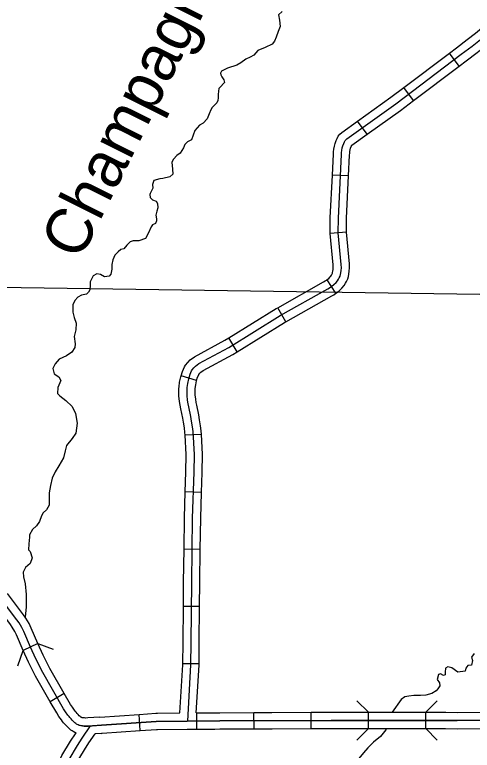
# Model space of a CAD drawing. Extents: x -492261 to -432772, y 1441225 to 1452922.
# Drawn here: x -458962.3 to -458841.6, y 1451430.4 to 1451624.2 of the extents above; entities that cross this region are included whole.
import ezdxf

# ---------------------------------------------------------------- set-up
doc = ezdxf.new("R2010")
doc.units = 0
doc.layers.add('Default', color=7, linetype='Continuous')

msp = doc.modelspace()

# ---------------------------------------------------------------- linework, layer by layer
at = {"layer": 'Default'}
for p, q in [((-458845.09, 1451610.65), (-458847.67, 1451614.06)), ((-458857.12, 1451601.54), (-458859.7, 1451604.96)), ((-458869.38, 1451592.66), (-458871.87, 1451596.15)), ((-458874.26, 1451581.68), (-458878.54, 1451581.89)), ((-458874.84, 1451566.91), (-458879.11, 1451566.51)), ((-458877.61, 1451550.78), (-458879.94, 1451554.37)), ((-458890.84, 1451543.25), (-458892.94, 1451546.98)), ((-458903.61, 1451535.39), (-458905.86, 1451539.04)), ((-458914.32, 1451527.78), (-458918.42, 1451529.01)), ((-458913.06, 1451513.62), (-458917.34, 1451513.37)), ((-458913.02, 1451498.35), (-458917.3, 1451498.49)), ((-458913.36, 1451483.31), (-458917.64, 1451483.37)), ((-458913.53, 1451468.24), (-458917.82, 1451468.27)), ((-458956.15, 1451458.5), (-458960.03, 1451456.68)), ((-458913.69, 1451453.14), (-458917.97, 1451453.2)), ((-458949.2, 1451445.33), (-458952.91, 1451443.19)), ((-458914.26, 1451435.98), (-458914.28, 1451440.26)), ((-458899.18, 1451436.05), (-458899.2, 1451440.33)), ((-458884.09, 1451436.11), (-458884.11, 1451440.4)), ((-458869.02, 1451436.14), (-458869.02, 1451440.42)), ((-458853.93, 1451436.14), (-458853.93, 1451440.42)), ((-458929.2, 1451435.58), (-458929.5, 1451439.85))]:
    msp.add_line(p, q, dxfattribs=at)
for points in [[(-458891.73, 1451624.99), (-458892.71, 1451624.09), (-458892.43, 1451622.77), (-458892.28, 1451621.03), (-458892.85, 1451619.76), (-458893.39, 1451618.26), (-458893.77, 1451617.22), (-458894.43, 1451616.43), (-458896.21, 1451615.54), (-458898.14, 1451614.73), (-458899.28, 1451613.5), (-458900.19, 1451612.94), (-458901.38, 1451612.49), (-458902.7, 1451611.51), (-458903.74, 1451610.86), (-458906.21, 1451610.07), (-458907.76, 1451609.32), (-458908.01, 1451608.76)], [(-458847.67, 1451614.06), (-458845.85, 1451615.44), (-458842.97, 1451617.6), (-458840.83, 1451619.29), (-458839.78, 1451620.14), (-458838.5, 1451621.24), (-458836.61, 1451622.99), (-458836.19, 1451623.41)], [(-458845.09, 1451610.65), (-458843.27, 1451612.02), (-458840.36, 1451614.2), (-458838.15, 1451615.94), (-458837.04, 1451616.84), (-458835.64, 1451618.04), (-458833.65, 1451619.89), (-458833.19, 1451620.34)], [(-458916.68, 1451438.11), (-458915.83, 1451452.87), (-458915.76, 1451458.81), (-458915.62, 1451474.67), (-458915.39, 1451491.57), (-458914.98, 1451503.65), (-458914.9, 1451508.32), (-458915.25, 1451514.34), (-458915.41, 1451515.59), (-458915.64, 1451517.14), (-458915.84, 1451518.34), (-458916.38, 1451520.83), (-458916.56, 1451521.66), (-458916.69, 1451522.59), (-458916.84, 1451523.87), (-458916.83, 1451525.65), (-458916.81, 1451525.94), (-458916.68, 1451527.05), (-458916.41, 1451528.26), (-458916.06, 1451529.45), (-458915.63, 1451530.36), (-458915.47, 1451530.62), (-458915.05, 1451531.17), (-458914.61, 1451531.62), (-458913.71, 1451532.27), (-458905.84, 1451536.54), (-458892.27, 1451544.9), (-458879.75, 1451551.95), (-458879.31, 1451552.22), (-458878.67, 1451552.64), (-458878.11, 1451553.08), (-458877.55, 1451553.6), (-458877.16, 1451554.06), (-458876.91, 1451554.48), (-458876.72, 1451554.84), (-458876.52, 1451555.33), (-458876.39, 1451555.75), (-458876.29, 1451556.2), (-458876.2, 1451556.82), (-458876.17, 1451557.49), (-458876.19, 1451558.38), (-458876.98, 1451566.73), (-458876.93, 1451570.6), (-458876.13, 1451587.31), (-458876.1, 1451587.87), (-458876.04, 1451588.42), (-458875.92, 1451589.07), (-458875.77, 1451589.62), (-458875.55, 1451590.25), (-458875.37, 1451590.67), (-458875.2, 1451591), (-458875.01, 1451591.23), (-458874.74, 1451591.48), (-458861.81, 1451600.68), (-458844.56, 1451613.73), (-458841.67, 1451615.9), (-458839.49, 1451617.61)], [(-458859.7, 1451604.96), (-458847.67, 1451614.06)], [(-458857.12, 1451601.54), (-458845.09, 1451610.65)], [(-458908.01, 1451608.76), (-458907.92, 1451608.29), (-458907.71, 1451607.83), (-458907.15, 1451607.04), (-458906.96, 1451606.33), (-458907.21, 1451606.04), (-458907.9, 1451605.28), (-458908.43, 1451604.69), (-458908.53, 1451604.03), (-458908.65, 1451603.14), (-458908.65, 1451602.25), (-458908.69, 1451601.56), (-458908.99, 1451600.95), (-458910.25, 1451599.68), (-458910.61, 1451599.13), (-458911.04, 1451598.09), (-458911.58, 1451596.78), (-458912.57, 1451595.58), (-458913.53, 1451595.1), (-458914.76, 1451593.69), (-458915.64, 1451591.2), (-458916.71, 1451590.69), (-458917.41, 1451590.01), (-458917.81, 1451589.06), (-458918.69, 1451587.66), (-458919.56, 1451587.04), (-458920.4, 1451586.1), (-458920.83, 1451585.28), (-458920.65, 1451583.51), (-458920.61, 1451582.19), (-458921.37, 1451581.46), (-458923.19, 1451581.04), (-458924.04, 1451580.93), (-458925.6, 1451580.49), (-458925.92, 1451579.45), (-458925.84, 1451578.51), (-458926.25, 1451577.75), (-458926.6, 1451577.05), (-458926.65, 1451576.82), (-458926.55, 1451575.99), (-458925.93, 1451575.41), (-458924.98, 1451575.03), (-458924.62, 1451574.46), (-458924.56, 1451573.32), (-458924.8, 1451572.42), (-458925.03, 1451571.36), (-458924.92, 1451570.36), (-458924.9, 1451569.9), (-458925.17, 1451569.2), (-458925.91, 1451568.78), (-458926.32, 1451568.26), (-458927.05, 1451566.52), (-458927.82, 1451565.18), (-458929.57, 1451564.62), (-458931.06, 1451564.58), (-458931.83, 1451564.31), (-458932.72, 1451563.45), (-458933.55, 1451562.52), (-458934.29, 1451562.3), (-458934.99, 1451561.68), (-458935.85, 1451560.79), (-458936.43, 1451559.63), (-458936.71, 1451558.39), (-458936.69, 1451557.73), (-458936.7, 1451557.13), (-458936.93, 1451555.84), (-458937.37, 1451555.28), (-458938.57, 1451555.11), (-458939.7, 1451555.74), (-458940.62, 1451555.89), (-458941.61, 1451555.38), (-458942.34, 1451553.81), (-458942.4, 1451552.8), (-458942.49, 1451551.68), (-458942.81, 1451551.04), (-458943.34, 1451550.54), (-458944.65, 1451550.25), (-458945.61, 1451549.74), (-458946.42, 1451548.86), (-458946.93, 1451547.73), (-458946.94, 1451545.78), (-458946.6, 1451544.43)], [(-458871.87, 1451596.15), (-458863.08, 1451602.41), (-458859.7, 1451604.96)], [(-458869.38, 1451592.66), (-458860.54, 1451598.95), (-458857.12, 1451601.54)], [(-458878.54, 1451581.89), (-458878.27, 1451587.43), (-458878.23, 1451588.04), (-458878.16, 1451588.73), (-458878.01, 1451589.54), (-458877.82, 1451590.26), (-458877.55, 1451591.03), (-458877.31, 1451591.59), (-458876.99, 1451592.19), (-458876.57, 1451592.71), (-458876.08, 1451593.15), (-458871.87, 1451596.15)], [(-458874.26, 1451581.68), (-458873.99, 1451587.2), (-458873.96, 1451587.69), (-458873.92, 1451588.11), (-458873.83, 1451588.6), (-458873.72, 1451588.98), (-458873.55, 1451589.47), (-458873.44, 1451589.74), (-458873.42, 1451589.78), (-458873.39, 1451589.8), (-458869.38, 1451592.66)], [(-458879.11, 1451566.51), (-458879.12, 1451566.64), (-458879.08, 1451570.67), (-458878.54, 1451581.89)], [(-458874.84, 1451566.82), (-458874.79, 1451570.54), (-458874.26, 1451581.68)], [(-458879.94, 1451554.37), (-458879.93, 1451554.38), (-458879.5, 1451554.71), (-458879.1, 1451555.08), (-458878.92, 1451555.3), (-458878.78, 1451555.53), (-458878.66, 1451555.76), (-458878.54, 1451556.05), (-458878.47, 1451556.29), (-458878.4, 1451556.59), (-458878.34, 1451557.02), (-458878.32, 1451557.51), (-458878.34, 1451558.25), (-458879.11, 1451566.51)], [(-458877.61, 1451550.78), (-458877.42, 1451550.89), (-458876.72, 1451551.45), (-458876, 1451552.12), (-458875.41, 1451552.81), (-458875.04, 1451553.43), (-458874.78, 1451553.93), (-458874.5, 1451554.61), (-458874.32, 1451555.2), (-458874.18, 1451555.81), (-458874.07, 1451556.62), (-458874.03, 1451557.47), (-458874.05, 1451558.5), (-458874.84, 1451566.91)], [(-458990.86, 1451552.72), (-458839.69, 1451550.51)], [(-458892.94, 1451546.98), (-458880.84, 1451553.8), (-458880.46, 1451554.03), (-458879.94, 1451554.37)], [(-458890.84, 1451543.25), (-458878.66, 1451550.11), (-458878.16, 1451550.41), (-458877.61, 1451550.78)], [(-458905.86, 1451539.04), (-458893.36, 1451546.75), (-458892.94, 1451546.98)], [(-458946.6, 1451544.43), (-458946.04, 1451542.93), (-458946.19, 1451541.18), (-458946.6, 1451539.37), (-458946.36, 1451537.46), (-458946.39, 1451536.54), (-458947.19, 1451535.24), (-458948.62, 1451534.34), (-458950.56, 1451533.43), (-458951.64, 1451532.21), (-458952.24, 1451530.93), (-458951.83, 1451529.54), (-458950.64, 1451528.8), (-458950.11, 1451527.84), (-458950.94, 1451525.96), (-458950.99, 1451524.39), (-458950.37, 1451523.78), (-458948.78, 1451522.53), (-458947.17, 1451520.97), (-458946.21, 1451519.11), (-458945.77, 1451516.61), (-458946.16, 1451513.97), (-458947.1, 1451512.57), (-458948.59, 1451510.7), (-458948.98, 1451509.26), (-458949.39, 1451507.45), (-458950.62, 1451505.33), (-458951.58, 1451503.79), (-458952.42, 1451502.11), (-458952.8, 1451500.16), (-458953.21, 1451498.26), (-458953.17, 1451496.84), (-458953.18, 1451494.95), (-458953.86, 1451493.7), (-458954.73, 1451492.96), (-458955.22, 1451492.15), (-458955.73, 1451490.71), (-458956.55, 1451489.52), (-458957.61, 1451488.57), (-458958.38, 1451487.18), (-458958.36, 1451486.58), (-458958.54, 1451484.75), (-458958.68, 1451483.2), (-458958.24, 1451482.76), (-458957.71, 1451481.08), (-458958.24, 1451479.61), (-458959.44, 1451478.55), (-458960.01, 1451477.31), (-458959.99, 1451476.06), (-458959.55, 1451474.28), (-458959.29, 1451471.48), (-458959.23, 1451468.16), (-458959.53, 1451465.47)], [(-458903.61, 1451535.39), (-458891.18, 1451543.06), (-458890.84, 1451543.25)], [(-458918.42, 1451529.01), (-458918.06, 1451530.21), (-458917.52, 1451531.38), (-458917.24, 1451531.83), (-458916.67, 1451532.59), (-458916, 1451533.25), (-458914.85, 1451534.08), (-458906.91, 1451538.39), (-458905.86, 1451539.04)], [(-458914.32, 1451527.78), (-458914.05, 1451528.68), (-458913.75, 1451529.33), (-458913.7, 1451529.41), (-458913.43, 1451529.76), (-458913.22, 1451529.98), (-458912.56, 1451530.45), (-458904.76, 1451534.68), (-458903.61, 1451535.39)], [(-458917.34, 1451513.37), (-458917.39, 1451514.14), (-458917.53, 1451515.3), (-458917.76, 1451516.8), (-458917.95, 1451517.93), (-458918.48, 1451520.38), (-458918.67, 1451521.28), (-458918.82, 1451522.31), (-458918.98, 1451523.76), (-458918.97, 1451525.74), (-458918.94, 1451526.14), (-458918.79, 1451527.4), (-458918.49, 1451528.8), (-458918.42, 1451529.01)], [(-458913.06, 1451513.62), (-458913.12, 1451514.53), (-458913.28, 1451515.88), (-458913.52, 1451517.48), (-458913.74, 1451518.74), (-458914.29, 1451521.28), (-458914.45, 1451522.04), (-458914.57, 1451522.86), (-458914.7, 1451523.99), (-458914.69, 1451525.57), (-458914.67, 1451525.74), (-458914.56, 1451526.69), (-458914.34, 1451527.72), (-458914.32, 1451527.78)], [(-458917.3, 1451498.49), (-458917.12, 1451503.7), (-458917.04, 1451508.28), (-458917.34, 1451513.37)], [(-458913.02, 1451498.35), (-458912.84, 1451503.59), (-458912.76, 1451508.37), (-458913.06, 1451513.62)], [(-458917.64, 1451483.37), (-458917.53, 1451491.62), (-458917.3, 1451498.49)], [(-458913.36, 1451483.31), (-458913.25, 1451491.52), (-458913.02, 1451498.35)], [(-458917.82, 1451468.27), (-458917.76, 1451474.69), (-458917.64, 1451483.37)], [(-458913.53, 1451468.24), (-458913.47, 1451474.65), (-458913.36, 1451483.31)], [(-458956.15, 1451458.5), (-458957.92, 1451462.61), (-458958.47, 1451463.78), (-458959.35, 1451465.18), (-458959.96, 1451466.04), (-458964.2, 1451471.66)], [(-458939.38, 1451437.02), (-458942.92, 1451436.78), (-458943.57, 1451436.76), (-458943.96, 1451436.76), (-458944.38, 1451436.8), (-458944.72, 1451436.84), (-458944.99, 1451436.89), (-458945.25, 1451436.97), (-458945.53, 1451437.07), (-458945.81, 1451437.22), (-458945.97, 1451437.32), (-458946.14, 1451437.44), (-458946.4, 1451437.65), (-458946.74, 1451437.95), (-458947.11, 1451438.32), (-458947.42, 1451438.66), (-458947.74, 1451439.04), (-458947.95, 1451439.3), (-458948.24, 1451439.69), (-458948.85, 1451440.53), (-458949.38, 1451441.36), (-458954.9, 1451450.91), (-458956.67, 1451454.5), (-458958.09, 1451457.58), (-458959.87, 1451461.73), (-458960.36, 1451462.75), (-458961.13, 1451463.99), (-458961.69, 1451464.77), (-458965.73, 1451470.1)], [(-458939.38, 1451437.02), (-458942.92, 1451436.78), (-458943.57, 1451436.76), (-458943.96, 1451436.76), (-458944.38, 1451436.8), (-458944.72, 1451436.84), (-458944.99, 1451436.89), (-458945.25, 1451436.97), (-458945.53, 1451437.07), (-458945.81, 1451437.22), (-458945.97, 1451437.32), (-458946.14, 1451437.44), (-458946.4, 1451437.65), (-458946.74, 1451437.95), (-458947.11, 1451438.32), (-458947.42, 1451438.66), (-458947.74, 1451439.04), (-458947.95, 1451439.3), (-458948.24, 1451439.69), (-458948.85, 1451440.53), (-458949.38, 1451441.36), (-458954.9, 1451450.91), (-458956.67, 1451454.5), (-458958.09, 1451457.58), (-458959.87, 1451461.73), (-458960.36, 1451462.75), (-458961.13, 1451463.99), (-458961.69, 1451464.77), (-458965.73, 1451470.1)], [(-458960.03, 1451456.68), (-458961.83, 1451460.85), (-458962.24, 1451461.72), (-458962.91, 1451462.8), (-458963.42, 1451463.5), (-458967.47, 1451468.85), (-458967.64, 1451469.1)], [(-458917.97, 1451453.2), (-458917.9, 1451458.83), (-458917.82, 1451468.27)], [(-458913.69, 1451453.14), (-458913.61, 1451458.79), (-458913.53, 1451468.24)], [(-458949.2, 1451445.33), (-458953.01, 1451451.92), (-458954.73, 1451455.42), (-458956.15, 1451458.5)], [(-458956.15, 1451458.5), (-458952.12, 1451457.04)], [(-458961.49, 1451452.65), (-458960.03, 1451456.68)], [(-458952.91, 1451443.19), (-458956.79, 1451449.9), (-458958.6, 1451453.57), (-458960.03, 1451456.68)], [(-458841.18, 1451455.87), (-458841.88, 1451454.97), (-458841.59, 1451454.03), (-458841.85, 1451452.79), (-458842.82, 1451452.71), (-458843.32, 1451452.03), (-458843.52, 1451451.2), (-458845.49, 1451450.95), (-458847.04, 1451452.09), (-458848.1, 1451452.35), (-458848.69, 1451452.04), (-458848.84, 1451450.95), (-458848.82, 1451450.32), (-458849.24, 1451450.08), (-458850, 1451450.55), (-458850.59, 1451450.33), (-458850.88, 1451449.04), (-458850.28, 1451448.16), (-458850.18, 1451447.39), (-458850.73, 1451446.6), (-458851.17, 1451446.1), (-458852.3, 1451445.4), (-458853.9, 1451444.96), (-458855.31, 1451444.83), (-458857.1, 1451444.83), (-458858.34, 1451444.69), (-458859.41, 1451444.51), (-458860.38, 1451443.75), (-458862.76, 1451440.42)], [(-458918.71, 1451440.23), (-458917.98, 1451452.95), (-458917.97, 1451453.2)], [(-458914.41, 1451440.26), (-458913.69, 1451452.8), (-458913.69, 1451453.14)], [(-458939.81, 1451439.14), (-458943.02, 1451438.92), (-458943.58, 1451438.9), (-458943.86, 1451438.91), (-458944.15, 1451438.93), (-458944.37, 1451438.96), (-458944.5, 1451438.98), (-458944.59, 1451439.01), (-458944.66, 1451439.03), (-458944.75, 1451439.08), (-458944.78, 1451439.1), (-458944.83, 1451439.14), (-458945.02, 1451439.29), (-458945.26, 1451439.51), (-458945.57, 1451439.81), (-458945.81, 1451440.08), (-458946.1, 1451440.41), (-458946.27, 1451440.62), (-458946.52, 1451440.95), (-458947.07, 1451441.73), (-458947.55, 1451442.48), (-458949.2, 1451445.33)], [(-458946.11, 1451435), (-458946.41, 1451435.11), (-458946.87, 1451435.35), (-458947.17, 1451435.54), (-458947.44, 1451435.74), (-458947.79, 1451436.02), (-458948.21, 1451436.4), (-458948.66, 1451436.84), (-458949.03, 1451437.25), (-458949.39, 1451437.67), (-458949.64, 1451437.97), (-458949.97, 1451438.42), (-458950.62, 1451439.33), (-458951.21, 1451440.25), (-458952.91, 1451443.19)], [(-458872.05, 1451443.45), (-458869.02, 1451440.42)], [(-458853.93, 1451440.42), (-458850.9, 1451443.45)], [(-458914.41, 1451440.26), (-458914.28, 1451440.26)], [(-458914.28, 1451440.26), (-458909.54, 1451440.29), (-458908.18, 1451440.29), (-458899.2, 1451440.33)], [(-458899.2, 1451440.33), (-458894.45, 1451440.35), (-458884.11, 1451440.4)], [(-458884.11, 1451440.4), (-458879.36, 1451440.42), (-458878.86, 1451440.42), (-458869.02, 1451440.42)], [(-458869.02, 1451440.42), (-458864.27, 1451440.42), (-458853.93, 1451440.42)], [(-458853.93, 1451440.42), (-458849.18, 1451440.42), (-458848.63, 1451440.42), (-458845.61, 1451440.36), (-458838.87, 1451440.43)], [(-458939.81, 1451439.14), (-458929.5, 1451439.85)], [(-458832.84, 1451438.36), (-458845.62, 1451438.21), (-458848.66, 1451438.28), (-458878.86, 1451438.28), (-458908.17, 1451438.15), (-458916.8, 1451438.11), (-458924.95, 1451438.02), (-458939.38, 1451437.02)], [(-458832.84, 1451438.36), (-458845.62, 1451438.21), (-458848.66, 1451438.28), (-458878.86, 1451438.28), (-458908.17, 1451438.15), (-458916.8, 1451438.11), (-458924.95, 1451438.02), (-458939.38, 1451437.02)], [(-458929.5, 1451439.85), (-458925.04, 1451440.16), (-458924.63, 1451440.17), (-458918.71, 1451440.23)], [(-458849.18, 1451438.28), (-458848.66, 1451438.28), (-458845.62, 1451438.21), (-458834.1, 1451438.34)], [(-458947.96, 1451427.94), (-458945.71, 1451431.68), (-458944.48, 1451433.58), (-458942.26, 1451436.82)], [(-458944.4, 1451436.8), (-458944.38, 1451436.8), (-458943.96, 1451436.76), (-458943.57, 1451436.76), (-458942.92, 1451436.78), (-458939.66, 1451437)], [(-458939.66, 1451437), (-458939.38, 1451437.02), (-458924.95, 1451438.02), (-458924.61, 1451438.03)], [(-458924.61, 1451438.03), (-458916.8, 1451438.11), (-458909.53, 1451438.14)], [(-458909.53, 1451438.14), (-458908.17, 1451438.15), (-458894.44, 1451438.21)], [(-458894.44, 1451438.21), (-458879.35, 1451438.28)], [(-458879.35, 1451438.28), (-458878.86, 1451438.28), (-458864.27, 1451438.28)], [(-458864.27, 1451438.28), (-458849.18, 1451438.28)], [(-458950.51, 1451427.7), (-458949.83, 1451428.99), (-458947.53, 1451432.82), (-458946.27, 1451434.77), (-458946.11, 1451435)], [(-458946.71, 1451425.7), (-458946.09, 1451426.89), (-458943.9, 1451430.55), (-458942.7, 1451432.39), (-458941.08, 1451434.76)], [(-458939.51, 1451434.86), (-458941.08, 1451434.76)], [(-458939.51, 1451434.86), (-458939.23, 1451434.88), (-458929.2, 1451435.58)], [(-458929.2, 1451435.58), (-458924.86, 1451435.88), (-458924.59, 1451435.88), (-458916.78, 1451435.97), (-458914.26, 1451435.98)], [(-458914.26, 1451435.98), (-458909.51, 1451436), (-458908.16, 1451436.01), (-458899.18, 1451436.05)], [(-458899.18, 1451436.05), (-458894.43, 1451436.07), (-458884.09, 1451436.11)], [(-458884.09, 1451436.11), (-458879.34, 1451436.13), (-458878.85, 1451436.13), (-458869.02, 1451436.14)], [(-458864.33, 1451436.14), (-458864.47, 1451435.77), (-458865.85, 1451434.03), (-458867.67, 1451432.56), (-458869.15, 1451431.06), (-458870.37, 1451429.77), (-458871.59, 1451428.25), (-458872.87, 1451426.58), (-458873.02, 1451424.69), (-458872.64, 1451423.43), (-458872.72, 1451421.86), (-458873.71, 1451420.28), (-458874.71, 1451417.93)], [(-458869.02, 1451436.14), (-458872.05, 1451433.1)], [(-458869.02, 1451436.14), (-458864.27, 1451436.14), (-458853.93, 1451436.14)], [(-458853.93, 1451436.14), (-458849.18, 1451436.14), (-458848.68, 1451436.14), (-458845.64, 1451436.07), (-458838.82, 1451436.15)], [(-458850.9, 1451433.11), (-458853.93, 1451436.14)]]:
    msp.add_lwpolyline(points, dxfattribs=at)

# ---------------------------------------------------------------- texts
msp.add_text('Champagnolle', height=12.0685, rotation=63.3997, dxfattribs=at).set_placement((-458945.13, 1451559.08))

doc.saveas('drawing.dxf')
